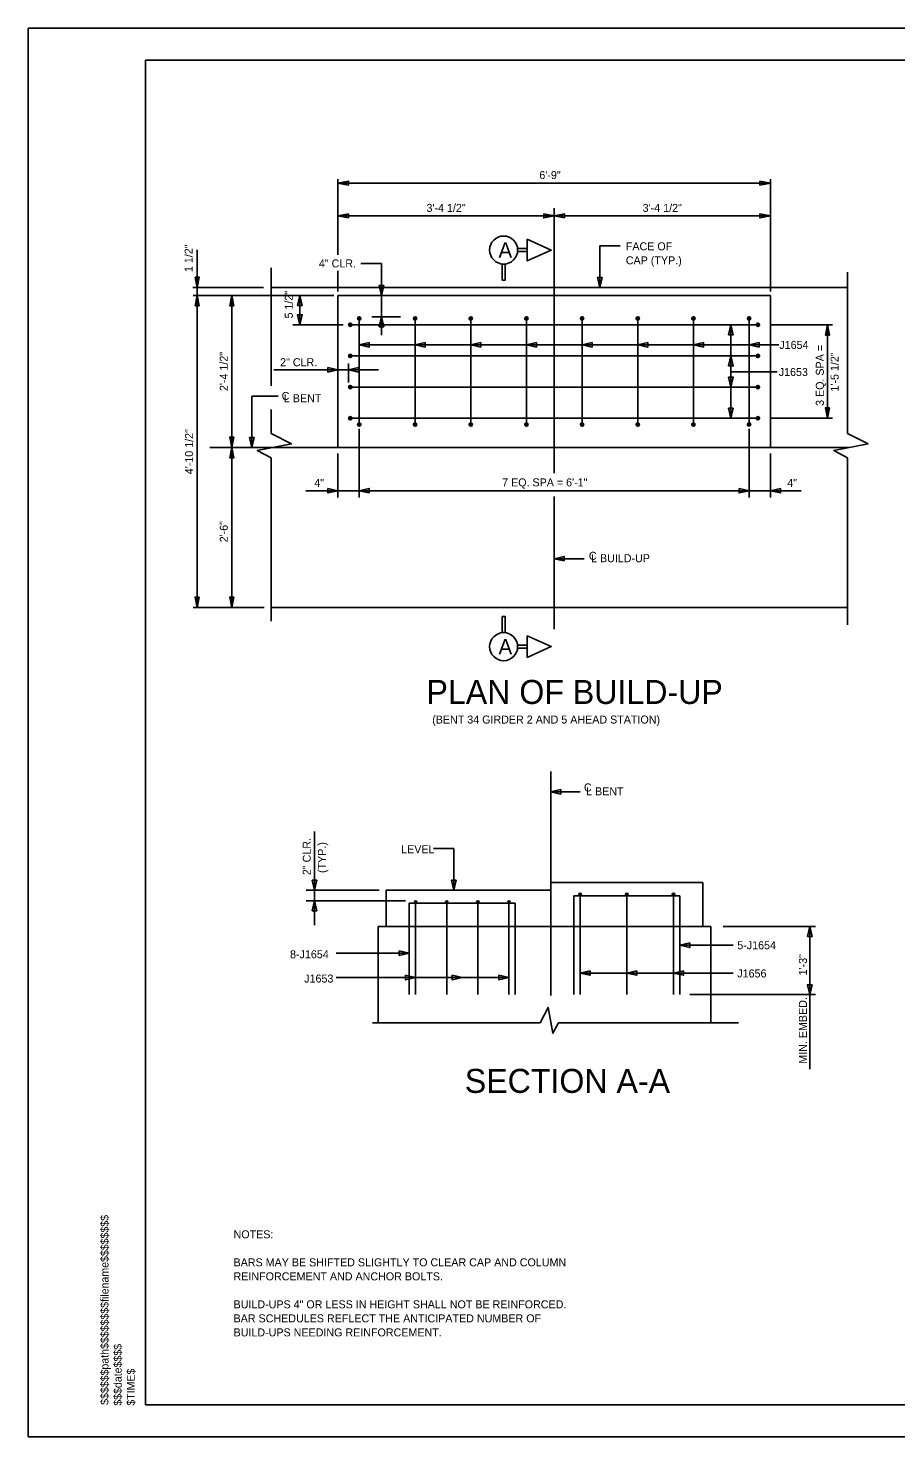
# Model space of a CAD drawing. Extents: x -133.1 to -97, y -110.1 to -88.1.
# Drawn here: x -133.14 to -119.6, y -110.1 to -88.1 of the extents above; entities that cross this region are included whole.
import ezdxf

# ---------------------------------------------------------------- set-up
doc = ezdxf.new("R2010")
doc.units = 0
for name, color, linetype in [('BR_AUTO DIMENSION', 7, 'Continuous'), ('BR_BORDER LINES', 7, 'Continuous'), ('BR_CENTER LINES', 7, 'Continuous'), ('BR_CONCRETE', 7, 'Continuous'), ('BR_REBAR', 7, 'Continuous'), ('BR_TEXT', 7, 'Continuous'), ('Default', 7, 'Continuous'), ('Level 31', 7, 'Continuous'), ('RD_SHT_ID', 7, 'Continuous')]:
    doc.layers.add(name, color=color, linetype=linetype)

msp = doc.modelspace()

# ---------------------------------------------------------------- linework, layer by layer
at = {"layer": 'BR_AUTO DIMENSION'}
for p, q in [((-128.305, -91.641), (-128.305, -90.459)), ((-128.305, -90.522), (-121.555, -90.522)), ((-121.555, -92.214), (-121.555, -90.459)), ((-128.305, -91.034), (-124.93, -91.034)), ((-124.93, -90.916), (-124.93, -91.28)), ((-121.555, -91.034), (-124.93, -91.034)), ((-124.216, -91.502), (-124.216, -92.152)), ((-124.216, -91.502), (-123.899, -91.502)), ((-130.504, -92.277), (-130.504, -91.563)), ((-128.305, -92.214), (-128.305, -91.895)), ((-127.625, -91.777), (-127.949, -91.777)), ((-127.625, -92.898), (-127.625, -91.777)), ((-129.47, -92.152), (-130.571, -92.152)), ((-128.367, -92.277), (-130.567, -92.277)), ((-130.504, -97.152), (-130.504, -92.277)), ((-129.962, -92.277), (-129.962, -94.652)), ((-128.899, -92.277), (-128.899, -92.735)), ((-127.776, -92.61), (-127.329, -92.61)), ((-128.226, -92.735), (-129.007, -92.735)), ((-122.171, -92.735), (-122.171, -94.194)), ((-121.565, -92.735), (-120.586, -92.735)), ((-120.664, -92.735), (-120.664, -94.194)), ((-127.972, -93.047), (-121.422, -93.047)), ((-127.67, -93.439), (-129.304, -93.439)), ((-128.138, -93.341), (-128.138, -93.639)), ((-122.171, -93.47), (-121.448, -93.47)), ((-129.648, -93.852), (-129.648, -94.652)), ((-129.236, -93.852), (-129.648, -93.852)), ((-127.972, -94.36), (-127.972, -95.43)), ((-121.888, -94.36), (-121.888, -95.43)), ((-121.565, -94.194), (-120.586, -94.194)), ((-130.019, -94.652), (-129.883, -94.652)), ((-129.962, -94.652), (-129.962, -97.152)), ((-128.305, -94.746), (-128.305, -95.43)), ((-121.555, -94.746), (-121.555, -95.43)), ((-128.808, -95.326), (-121.072, -95.326)), ((-124.93, -96.388), (-124.459, -96.388)), ((-129.459, -97.152), (-130.567, -97.152)), ((-124.983, -100.029), (-124.524, -100.029)), ((-128.671, -100.648), (-128.671, -102.113)), ((-126.811, -100.915), (-126.494, -100.915)), ((-126.494, -100.915), (-126.494, -101.565)), ((-127.663, -101.565), (-128.802, -101.565)), ((-127.251, -101.731), (-128.802, -101.731)), ((-122.291, -102.135), (-120.85, -102.135)), ((-120.94, -102.135), (-120.94, -104.361)), ((-122.968, -102.425), (-122.134, -102.425)), ((-127.192, -102.55), (-128.334, -102.55)), ((-125.635, -102.93), (-128.334, -102.93)), ((-126.364, -102.93), (-126.444, -102.93)), ((-124.525, -102.859), (-122.137, -102.859)), ((-123.796, -102.859), (-123.716, -102.859)), ((-122.796, -102.859), (-122.716, -102.859)), ((-122.812, -103.197), (-120.85, -103.197))]:
    msp.add_line(p, q, dxfattribs=at)
for points in [[(-128.142, -90.553), (-128.305, -90.522), (-128.142, -90.49)], [(-121.717, -90.49), (-121.555, -90.522), (-121.717, -90.553)], [(-128.142, -91.065), (-128.305, -91.034), (-128.142, -91.003)], [(-125.092, -91.003), (-124.93, -91.034), (-125.092, -91.065)], [(-124.767, -91.065), (-124.93, -91.034), (-124.767, -91.003)], [(-121.717, -91.003), (-121.555, -91.034), (-121.717, -91.065)], [(-130.535, -91.989), (-130.504, -92.152), (-130.473, -91.989)], [(-127.589, -92.121), (-127.625, -92.277), (-127.661, -92.121)], [(-124.18, -91.996), (-124.216, -92.152), (-124.252, -91.996)], [(-130.535, -92.439), (-130.504, -92.277), (-130.473, -92.439)], [(-129.994, -92.439), (-129.962, -92.277), (-129.931, -92.439)], [(-128.863, -92.433), (-128.899, -92.277), (-128.935, -92.433)], [(-128.935, -92.579), (-128.899, -92.735), (-128.863, -92.579)], [(-127.661, -92.766), (-127.625, -92.61), (-127.589, -92.766)], [(-122.207, -92.891), (-122.171, -92.735), (-122.135, -92.891)], [(-120.695, -92.898), (-120.664, -92.735), (-120.632, -92.898)], [(-127.816, -93.011), (-127.972, -93.047), (-127.816, -93.083)], [(-126.946, -93.011), (-127.102, -93.047), (-126.946, -93.083)], [(-126.077, -93.011), (-126.233, -93.047), (-126.077, -93.083)], [(-125.208, -93.011), (-125.364, -93.047), (-125.208, -93.083)], [(-124.339, -93.011), (-124.495, -93.047), (-124.339, -93.083)], [(-123.47, -93.011), (-123.626, -93.047), (-123.47, -93.083)], [(-122.601, -93.011), (-122.757, -93.047), (-122.601, -93.083)], [(-121.732, -93.011), (-121.888, -93.047), (-121.732, -93.083)], [(-122.207, -93.377), (-122.171, -93.221), (-122.135, -93.377)], [(-128.461, -93.475), (-128.305, -93.439), (-128.461, -93.403)], [(-127.982, -93.403), (-128.138, -93.439), (-127.982, -93.475)], [(-122.207, -93.551), (-122.171, -93.707), (-122.135, -93.551)], [(-122.135, -94.038), (-122.171, -94.194), (-122.207, -94.038)], [(-120.632, -94.031), (-120.664, -94.194), (-120.695, -94.031)], [(-129.931, -94.489), (-129.962, -94.652), (-129.994, -94.489)], [(-129.612, -94.496), (-129.648, -94.652), (-129.684, -94.496)], [(-129.994, -94.814), (-129.962, -94.652), (-129.931, -94.814)], [(-128.461, -95.29), (-128.305, -95.326), (-128.461, -95.362)], [(-127.816, -95.362), (-127.972, -95.326), (-127.816, -95.29)], [(-122.044, -95.29), (-121.888, -95.326), (-122.044, -95.362)], [(-121.399, -95.29), (-121.555, -95.326), (-121.399, -95.362)], [(-124.774, -96.424), (-124.93, -96.388), (-124.774, -96.352)], [(-130.473, -96.989), (-130.504, -97.152), (-130.535, -96.989)], [(-129.931, -96.989), (-129.962, -97.152), (-129.994, -96.989)], [(-124.827, -100.065), (-124.983, -100.029), (-124.827, -99.993)], [(-128.635, -101.409), (-128.671, -101.565), (-128.707, -101.409)], [(-126.458, -101.409), (-126.494, -101.565), (-126.53, -101.409)], [(-128.707, -101.887), (-128.671, -101.731), (-128.635, -101.887)], [(-120.976, -102.291), (-120.94, -102.135), (-120.904, -102.291)], [(-127.348, -102.514), (-127.192, -102.55), (-127.348, -102.586)], [(-122.812, -102.389), (-122.968, -102.425), (-122.812, -102.461)], [(-127.249, -102.894), (-127.093, -102.93), (-127.249, -102.966)], [(-126.52, -102.894), (-126.364, -102.93), (-126.52, -102.966)], [(-125.791, -102.894), (-125.635, -102.93), (-125.791, -102.966)], [(-124.369, -102.823), (-124.525, -102.859), (-124.369, -102.895)], [(-123.64, -102.823), (-123.796, -102.859), (-123.64, -102.895)], [(-122.911, -102.823), (-123.067, -102.859), (-122.911, -102.895)], [(-120.904, -103.041), (-120.94, -103.197), (-120.976, -103.041)]]:
    msp.add_lwpolyline(points, close=True, dxfattribs=at)
at = {"layer": 'BR_BORDER LINES'}
for p, q in [((-97.642, -88.603), (-131.308, -88.603)), ((-131.308, -109.603), (-131.308, -88.603)), ((-131.308, -109.603), (-97.642, -109.603))]:
    msp.add_line(p, q, dxfattribs=at)
at = {"layer": 'BR_CENTER LINES'}
for p, q in [((-124.93, -91.284), (-124.93, -95.05)), ((-130.304, -94.652), (-128.45, -94.652)), ((-124.93, -95.418), (-124.93, -97.491)), ((-124.983, -103.211), (-124.983, -99.713))]:
    msp.add_line(p, q, dxfattribs=at)
at = {"layer": 'BR_CONCRETE'}
for p, q in [((-129.349, -92.152), (-120.35, -92.152)), ((-128.305, -92.277), (-121.555, -92.277)), ((-128.305, -92.277), (-128.305, -94.652)), ((-121.555, -92.277), (-121.555, -94.652)), ((-128.305, -94.652), (-129.33, -94.652)), ((-128.305, -94.652), (-121.555, -94.652)), ((-121.555, -94.652), (-120.33, -94.652)), ((-129.349, -97.152), (-120.35, -97.152)), ((-127.552, -101.565), (-127.552, -102.135)), ((-127.552, -101.565), (-124.983, -101.565)), ((-124.983, -101.447), (-122.608, -101.447)), ((-124.983, -101.447), (-124.983, -102.135)), ((-122.608, -101.447), (-122.608, -102.135)), ((-127.677, -103.637), (-127.677, -102.135)), ((-127.677, -102.135), (-122.483, -102.135)), ((-127.233, -102.135), (-122.483, -102.135)), ((-122.483, -103.637), (-122.483, -102.135))]:
    msp.add_line(p, q, dxfattribs=at)
at = {"layer": 'BR_REBAR'}
for p, q in [((-127.972, -94.319), (-127.972, -92.61)), ((-127.102, -94.319), (-127.102, -92.61)), ((-126.233, -94.319), (-126.233, -92.61)), ((-125.364, -94.319), (-125.364, -92.61)), ((-124.495, -94.319), (-124.495, -92.61)), ((-123.626, -94.319), (-123.626, -92.61)), ((-122.757, -94.319), (-122.757, -92.61)), ((-121.888, -94.319), (-121.888, -92.61)), ((-128.138, -92.735), (-121.722, -92.735)), ((-128.138, -93.221), (-121.722, -93.221)), ((-128.138, -93.707), (-121.722, -93.707)), ((-128.138, -94.194), (-121.722, -94.194)), ((-124.525, -101.614), (-124.525, -103.197)), ((-123.796, -101.614), (-123.796, -103.197)), ((-123.067, -101.614), (-123.067, -103.197)), ((-127.192, -101.77), (-127.192, -103.197)), ((-127.192, -101.77), (-125.536, -101.77)), ((-127.093, -101.731), (-127.093, -103.197)), ((-126.607, -101.731), (-126.607, -103.197)), ((-126.121, -101.731), (-126.121, -103.197)), ((-125.635, -101.731), (-125.635, -103.197)), ((-125.536, -101.77), (-125.536, -103.197)), ((-124.624, -101.653), (-124.624, -103.197)), ((-124.624, -101.653), (-122.968, -101.653)), ((-122.968, -101.653), (-122.968, -103.197))]:
    msp.add_line(p, q, dxfattribs=at)
for centre, radius in [((-127.972, -92.636), 0.0261), ((-127.102, -92.636), 0.0261), ((-126.233, -92.636), 0.0261), ((-125.364, -92.636), 0.0261), ((-124.495, -92.636), 0.0261), ((-123.626, -92.636), 0.0261), ((-122.757, -92.636), 0.0261), ((-121.888, -92.636), 0.0261), ((-128.112, -92.735), 0.026), ((-121.748, -92.735), 0.026), ((-128.112, -93.221), 0.026), ((-121.748, -93.221), 0.026), ((-128.112, -93.707), 0.026), ((-121.748, -93.707), 0.026), ((-128.112, -94.194), 0.026), ((-127.972, -94.293), 0.0261), ((-127.102, -94.293), 0.0261), ((-126.233, -94.293), 0.0261), ((-125.364, -94.293), 0.0261), ((-124.495, -94.293), 0.0261), ((-123.626, -94.293), 0.0261), ((-122.757, -94.293), 0.0261), ((-121.888, -94.292), 0.0261), ((-121.748, -94.194), 0.026), ((-124.525, -101.633), 0.0195), ((-123.796, -101.633), 0.0195), ((-123.067, -101.633), 0.0195), ((-127.093, -101.751), 0.0195), ((-126.607, -101.751), 0.0195), ((-126.121, -101.751), 0.0195), ((-125.635, -101.751), 0.0195)]:
    msp.add_circle(centre, radius, dxfattribs=at)
at = {"layer": 'BR_TEXT'}
msp.add_line((-126.494, -101.565), (-126.494, -101.5), dxfattribs=at)
for points in [[(-125.35, -91.399), (-124.974, -91.568), (-125.35, -91.737)], [(-125.5, -91.593), (-125.35, -91.593), (-125.35, -91.543), (-125.5, -91.543)], [(-125.744, -92.037), (-125.694, -92.037), (-125.694, -91.787), (-125.744, -91.787)], [(-125.744, -97.293), (-125.694, -97.293), (-125.694, -97.543), (-125.744, -97.543)], [(-125.35, -97.931), (-124.974, -97.762), (-125.35, -97.593)], [(-125.5, -97.737), (-125.35, -97.737), (-125.35, -97.787), (-125.5, -97.787)]]:
    msp.add_lwpolyline(points, close=True, dxfattribs=at)
for centre in [(-125.719, -91.568), (-125.719, -97.762)]:
    msp.add_circle(centre, 0.219, dxfattribs=at)
at = {"layer": 'Default'}
for p, q in [((-129.349, -91.847), (-129.349, -93.687)), ((-120.35, -91.912), (-120.35, -94.431)), ((-129.349, -94.058), (-129.349, -94.431)), ((-129.349, -94.814), (-129.349, -97.364)), ((-120.35, -94.814), (-120.35, -97.42)), ((-127.766, -103.637), (-125.149, -103.637)), ((-124.862, -103.637), (-122.052, -103.637))]:
    msp.add_line(p, q, dxfattribs=at)
for points in [[(-129.349, -94.814), (-129.566, -94.696), (-129.03, -94.595), (-129.349, -94.431)], [(-120.35, -94.814), (-120.566, -94.696), (-120.03, -94.595), (-120.35, -94.431)], [(-124.862, -103.637), (-124.95, -103.799), (-125.026, -103.397), (-125.149, -103.637)]]:
    msp.add_lwpolyline(points, dxfattribs=at)
at = {"layer": 'Level 31'}
msp.add_lwpolyline([(-133.141, -110.103), (-97.141, -110.103), (-97.141, -88.103), (-133.141, -88.103)], close=True, dxfattribs=at)

# ---------------------------------------------------------------- texts
at = {"layer": 'BR_AUTO DIMENSION'}
for s, p in [('6\'-9"', (-125.161, -90.459)), ('3\'-4 1/2"', (-126.923, -90.972)), ('3\'-4 1/2"', (-123.548, -90.972)), ('FACE OF', (-123.811, -91.572)), ('4" CLR.', (-128.603, -91.839)), ('CAP (TYP.)', (-123.811, -91.791)), ('J1654', (-121.415, -93.112)), ('2" CLR.', (-129.208, -93.382)), ('J1653', (-121.424, -93.535)), ('7 EQ. SPA = 6\'-1"', (-125.742, -95.259)), ('C', (-124.388, -96.406)), ('L BUILD-UP', (-124.354, -96.443)), ('(BENT 34 GIRDER 2 AND 5 AHEAD STATION)', (-126.834, -98.963)), ('C', (-124.465, -100.023)), ('L BENT', (-124.431, -100.084)), ('LEVEL', (-127.318, -100.988)), ('8-J1654', (-129.053, -102.629)), ('5-J1654', (-122.071, -102.488)), ('J1653', (-128.832, -103.008)), ('J1656', (-122.071, -102.928)), ('NOTES:', (-129.935, -107.002)), ('BARS MAY BE SHIFTED SLIGHTLY TO CLEAR CAP AND COLUMN', (-129.935, -107.44)), ('REINFORCEMENT AND ANCHOR BOLTS.', (-129.935, -107.659)), ('BUILD-UPS 4" OR LESS IN HEIGHT SHALL NOT BE REINFORCED.', (-129.935, -108.096)), ('BAR SCHEDULES REFLECT THE ANTICIPATED NUMBER OF', (-129.935, -108.315)), ('BUILD-UPS NEEDING REINFORCEMENT.', (-129.935, -108.534))]:
    msp.add_text(s, height=0.125, dxfattribs=at).set_placement(p)
for s, rotation, p in [('3 EQ. SPA =', 90, (-120.72, -94.002)), ('2\'-4 1/2"', 90, (-130.025, -93.77)), ('1\'-5 1/2"', 90, (-120.489, -93.778)), ('4\'-10 1/2"', 90, (-130.567, -95.069)), ('4"', 360, (-128.675, -95.267)), ('4"', 360, (-121.291, -95.267)), ('2\'-6"', 90, (-130.025, -96.133)), ('2" CLR.', 90, (-128.73, -101.33)), ('(TYP.)', 90, (-128.493, -101.297)), ('1\'-3" ', 90, (-120.984, -102.896)), ('MIN. EMBED.', 90, (-120.984, -104.275))]:
    msp.add_text(s, height=0.125, rotation=rotation, dxfattribs=at).set_placement(p)
at = {"layer": 'BR_TEXT'}
for s, rotation, p in [('1 1/2"', 90, (-130.573, -91.912)), ('5 1/2"', 90, (-129.01, -92.637)), ('C', 360, (-129.184, -93.909)), ('L BENT', 360, (-129.149, -93.945))]:
    msp.add_text(s, height=0.125, rotation=rotation, dxfattribs=at).set_placement(p)
for s, height, p in [('A', 0.24, (-125.799, -91.688)), ('A', 0.24, (-125.799, -97.882)), ('PLAN OF BUILD-UP', 0.375, (-126.923, -98.657)), ('SECTION A-A', 0.375, (-126.325, -104.731))]:
    msp.add_text(s, height=height, dxfattribs=at).set_placement(p)
at = {"layer": 'RD_SHT_ID'}
for s, height, p in [('$$$$$$path$$$$$$$$filename$$$$$$$$', 0.12347, (-131.887, -109.603)), ('$$$date$$$$', 0.12347, (-131.682, -109.616)), ('$TIME$', 0.1235, (-131.477, -109.616))]:
    msp.add_text(s, height=height, rotation=90, dxfattribs=at).set_placement(p)

doc.saveas('drawing.dxf')
